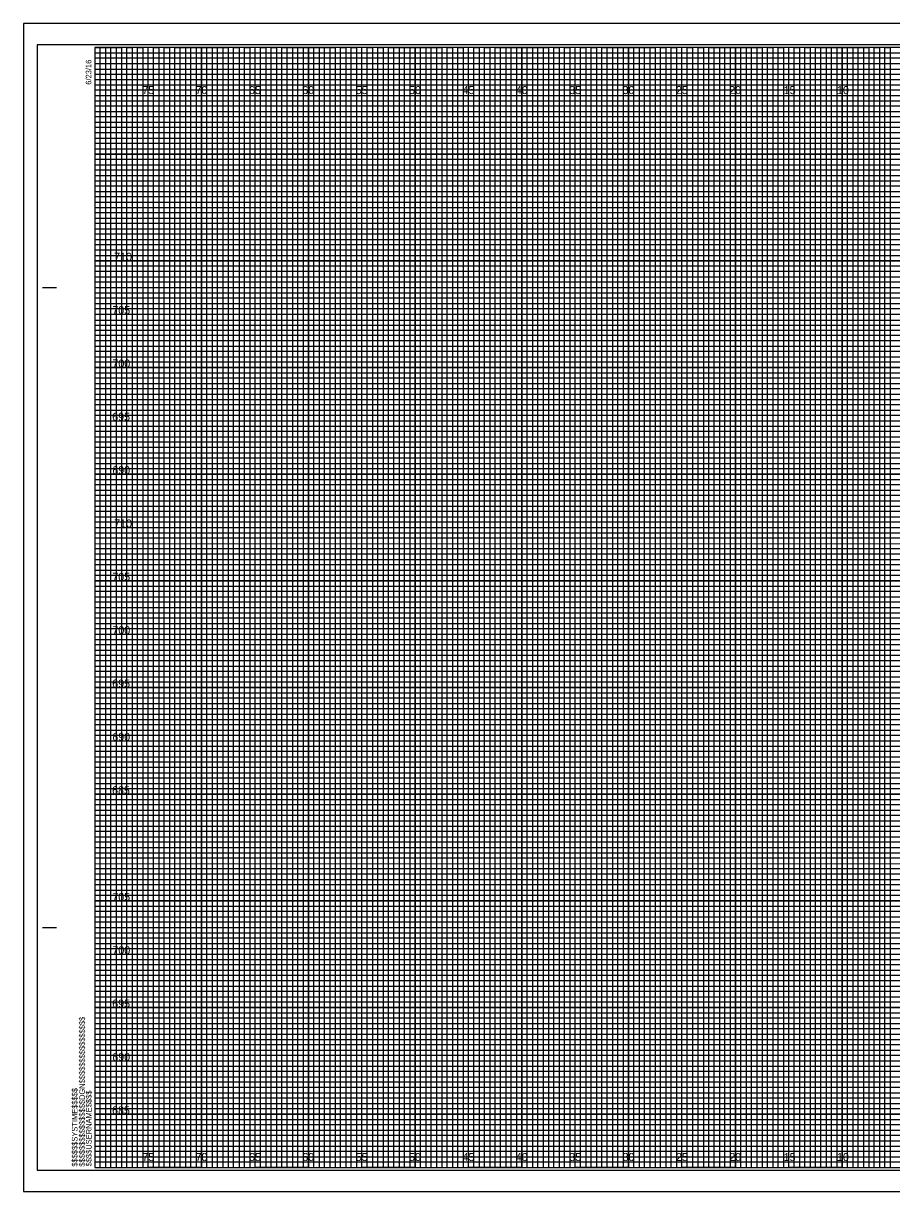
# Model space of a CAD drawing. Extents: x -7 to 162, y 108 to 217.
# Drawn here: x -6.7 to 74.6, y 107.8 to 217.2 of the extents above; entities that cross this region are included whole.
import ezdxf

# ---------------------------------------------------------------- set-up
doc = ezdxf.new("R2010")
doc.units = 0
for name, color, linetype in [('Exist Cross Section Cell', 7, 'Continuous'), ('Exist XS Ground Line', 7, 'Continuous'), ('Prop CMT Pvmt Course 1', 7, 'Continuous'), ('Prop CMT Pvmt Course 3', 7, 'Continuous'), ('Prop CMT Pvmt Surface', 7, 'Continuous'), ('Prop CMT Pvmt Surface Shoulder', 7, 'Continuous'), ('Prop CMT Shld Paved Course 1', 7, 'Continuous'), ('Prop CMT Shld Paved Course 2', 7, 'Continuous'), ('Prop CMT Shld Paved Course 3', 7, 'Continuous'), ('Prop CMT Subgrade Earthwork', 7, 'Continuous'), ('Scratch_Level_8', 7, 'Continuous')]:
    doc.layers.add(name, color=color, linetype=linetype)

msp = doc.modelspace()

# ---------------------------------------------------------------- linework, layer by layer
at = {"layer": 'Exist XS Ground Line'}
for p, q in [((5, 215), (0, 215)), ((5, 110), (5, 215)), ((15, 215), (10, 215)), ((10, 215), (10, 110)), ((15, 110), (15, 215)), ((25, 215), (20, 215)), ((20, 215), (20, 110)), ((25, 110), (25, 215)), ((35, 215), (30, 215)), ((30, 215), (30, 110)), ((35, 110), (35, 215)), ((45, 215), (40, 215)), ((40, 215), (40, 110)), ((45, 110), (45, 215)), ((55, 215), (50, 215)), ((50, 215), (50, 110)), ((55, 110), (55, 215)), ((65, 215), (60, 215)), ((60, 215), (60, 110)), ((65, 110), (65, 215)), ((75, 215), (70, 215)), ((70, 215), (70, 110)), ((10, 110), (5, 110)), ((20, 110), (15, 110)), ((30, 110), (25, 110)), ((40, 110), (35, 110)), ((50, 110), (45, 110)), ((60, 110), (55, 110)), ((70, 110), (65, 110))]:
    msp.add_line(p, q, dxfattribs=at)
for points in [[(0, 210), (160, 210), (160, 205), (0, 205)], [(0, 200), (160, 200), (160, 195), (0, 195)], [(0, 190), (160, 190), (160, 185), (0, 185)], [(0, 180), (160, 180), (160, 175), (0, 175)], [(0, 170), (160, 170), (160, 165), (0, 165)], [(0, 160), (160, 160), (160, 155), (0, 155)], [(0, 150), (160, 150), (160, 145), (0, 145)], [(0, 140), (160, 140), (160, 135), (0, 135)], [(0, 130), (160, 130), (160, 125), (0, 125)], [(0, 120), (160, 120), (160, 115), (0, 115)]]:
    msp.add_lwpolyline(points, dxfattribs=at)
at = {"layer": 'Prop CMT Pvmt Course 3'}
msp.add_lwpolyline([(-6.7, 107.75), (161.65, 107.75), (161.65, 217.25), (-6.7, 217.25)], close=True, dxfattribs=at)
at = {"layer": 'Prop CMT Pvmt Surface'}
for p, q in [((5, 110), (5, 215)), ((10, 110), (10, 215)), ((15, 110), (15, 215)), ((20, 110), (20, 215)), ((25, 110), (25, 215)), ((30, 110), (30, 215)), ((35, 110), (35, 215)), ((40, 110), (40, 215)), ((45, 110), (45, 215)), ((50, 110), (50, 215)), ((55, 110), (55, 215)), ((60, 110), (60, 215)), ((65, 110), (65, 215)), ((70, 110), (70, 215)), ((0, 210), (160, 210)), ((0, 205), (160, 205)), ((0, 200), (160, 200)), ((0, 195), (160, 195)), ((0, 190), (160, 190)), ((0, 185), (160, 185)), ((0, 180), (160, 180)), ((0, 175), (160, 175)), ((0, 170), (160, 170)), ((0, 165), (160, 165)), ((0, 160), (160, 160)), ((0, 155), (160, 155)), ((0, 150), (160, 150)), ((0, 145), (160, 145)), ((0, 140), (160, 140)), ((0, 135), (160, 135)), ((0, 130), (160, 130)), ((0, 125), (160, 125)), ((0, 120), (160, 120)), ((0, 115), (160, 115))]:
    msp.add_line(p, q, dxfattribs=at)
at = {"layer": 'Prop CMT Pvmt Surface Shoulder'}
for p, q in [((161.65, 217.25), (-6.7, 217.25)), ((-6.7, 217.25), (-6.7, 107.75)), ((-6.7, 107.75), (161.65, 107.75))]:
    msp.add_line(p, q, dxfattribs=at)
at = {"layer": 'Prop CMT Shld Paved Course 1'}
for p, q in [((0, 214.5), (130, 214.5)), ((130, 213.99), (0, 213.99)), ((0, 213.99), (0, 213.5)), ((0, 213.5), (130, 213.5)), ((130, 212.94), (0, 212.94)), ((0, 212.94), (0, 212)), ((0, 212), (160, 212))]:
    msp.add_line(p, q, dxfattribs=at)
for points in [[(0, 211.5), (135, 211.5), (160, 211.5), (160, 211), (0, 211)], [(0, 210.5), (160, 210.5), (160, 209.5), (0, 209.5)], [(0, 209), (160, 209), (160, 208.5), (0, 208.49)], [(0, 208), (160, 208), (160, 207), (0, 207)], [(0, 206.5), (160, 206.5), (160, 206), (0, 206)], [(0, 205.5), (160, 205.5), (160, 204.5), (0, 204.5)], [(0, 204), (160, 204), (160, 203.5), (0, 203.5)], [(0, 203), (160, 203), (160, 202), (0, 202)], [(0, 201.5), (160, 201.5), (160, 201), (0, 201)], [(0, 200.5), (160, 200.5), (160, 199.5), (0, 199.5)], [(0, 199), (160, 199), (160, 198.5), (0, 198.5)], [(0, 198), (160, 198), (160, 196.97), (160, 196.5), (160, 196), (0, 196)], [(0, 197), (160, 197), (160, 196.5), (0, 196.5)], [(0, 195.5), (160, 195.5), (160, 194.5), (0, 194.52)], [(0, 194.52), (160, 194.5), (160, 194), (0, 194)], [(0, 193.5), (160, 193.5), (160, 193), (0, 193)], [(0, 192), (160, 192), (160, 191.5), (0, 191.5)], [(0, 191), (160, 191), (160, 190.5), (0, 190.5)], [(-0.04, 189.44), (160, 189.44), (160, 188.94), (-0.04, 188.94)], [(0, 188.5), (160, 188.5), (160, 188), (0, 188)], [(0, 187), (160, 187), (160, 186.5), (0, 186.5)], [(0, 186), (160, 186), (160, 185.5), (0, 185.5)], [(0, 184.5), (160, 184.5), (160, 184), (0, 184)], [(0, 183.5), (160, 183.5), (160, 183), (0, 183)], [(0, 182), (160, 182), (160, 181.5), (0, 181.5)], [(0, 181), (160, 181), (160, 180.5), (0, 180.5)], [(0, 179.5), (160, 179.5), (160, 178.99), (0, 179)], [(0, 178.5), (160, 178.5), (160, 178), (0, 178)], [(0, 177), (160, 177), (160, 176.5), (0, 176.5)], [(0, 176), (160, 176), (160, 175.5), (0, 175.5)], [(0, 174.5), (160, 174.5), (160, 174), (0, 174)], [(0, 173.5), (160, 173.5), (160, 173), (0, 173)], [(0, 172), (160, 172), (160, 171.5), (0, 171.5)], [(0, 171), (160, 171), (160, 170.5), (0, 170.5)], [(0, 169.5), (160, 169.5), (160, 169), (0, 169)], [(0, 168.5), (160.03, 168.46), (160, 168), (0, 168)], [(0, 167), (160, 167), (160, 166.5), (0, 166.5)], [(0, 166), (160, 166), (160, 165.5), (0, 165.5)], [(0, 164.5), (160, 164.5), (160, 164), (0, 164)], [(0, 163.5), (160, 163.5), (160, 163), (0, 163)], [(0, 162), (160, 162), (160, 161.5), (0, 161.5)], [(0, 161), (160, 161), (160, 160.5), (0, 160.5)], [(0, 159.5), (160, 159.5), (160, 159), (0, 159)], [(0, 158.5), (160, 158.5), (160, 158), (0, 158)], [(0, 157), (160, 157), (160, 156.5), (0, 156.5)], [(0, 156), (160, 156), (160, 155.5), (0, 155.5)], [(0, 154.5), (160, 154.5), (160, 154), (0, 154)], [(0, 153.5), (160, 153.5), (160, 153), (0, 153)], [(0, 152), (160, 152), (160, 151.5), (0, 151.5)], [(0, 151), (160, 151), (160, 150.5), (0, 150.5)], [(0, 149.5), (160, 149.5), (160, 148.99), (0, 149)], [(0, 148.5), (160, 148.5), (160, 148), (0, 148)], [(0, 147), (160, 147), (160, 146.5), (0, 146.5)], [(0, 146), (160, 146), (160, 145.5), (0, 145.5)], [(0, 144.5), (160, 144.5), (160, 144), (0, 144)], [(0, 143.5), (160, 143.5), (160, 143), (0, 143)], [(0, 142), (160, 142), (160, 141.5), (0, 141.5)], [(0, 141), (160, 141), (160, 140.5), (0, 140.5)], [(0, 139.5), (160, 139.5), (160, 139), (0, 139)], [(0, 138.5), (160.03, 138.46), (160, 138), (0, 138)], [(0, 137), (160, 137), (160, 136.5), (0, 136.5)], [(0, 136), (160, 136), (160, 135.5), (0, 135.5)], [(0, 134.5), (160, 134.5), (160, 134), (0, 134)], [(0, 133.5), (160, 133.5), (160, 133), (0, 133)], [(0, 132), (160, 132), (160, 131.5), (0, 131.5)], [(0, 131), (160, 131), (160, 130.5), (0, 130.5)], [(0, 129.5), (160, 129.5), (160, 129), (0, 129)], [(0, 128.5), (160, 128.5), (160, 128), (0, 128)], [(0, 127), (160, 127), (160, 126.5), (0, 126.5)], [(0, 126), (160, 126), (160, 125.5), (0, 125.5)], [(0, 124.5), (160, 124.5), (160, 124), (0, 124)], [(0, 123.5), (160, 123.5), (160, 123), (0, 123)], [(0, 122), (160, 122), (160, 121.5), (0, 121.5)], [(0, 121), (160, 121), (160, 120.5), (0, 120.5)], [(0, 119.5), (160, 119.5), (160, 119), (0, 119)], [(0, 118.5), (160, 118.5), (160, 118), (0, 118)], [(0, 117), (160, 117), (160, 116.5), (0, 116.5)], [(0, 116), (160, 116), (160, 115.5), (0, 115.5)], [(0, 114.5), (160, 114.5), (160, 114), (0, 114)], [(0, 113.5), (160, 113.5), (160, 113), (0, 113)], [(0, 112), (160, 112), (160, 111.5), (0, 111.5)], [(0, 111), (160, 111), (160, 110.5), (0, 110.5)]]:
    msp.add_lwpolyline(points, dxfattribs=at)
at = {"layer": 'Prop CMT Shld Paved Course 2'}
for p, q in [((-4.9, 192.5), (-3.65, 192.5)), ((-4.85, 192.5), (-3.6, 192.5)), ((-4.9, 132.5), (-3.65, 132.5)), ((-4.85, 132.5), (-3.6, 132.5)), ((0, 110), (0, 110)), ((0, 110), (0, 110)), ((0, 110), (0, 110)), ((0, 110), (0, 110)), ((0, 110), (0, 110)), ((0, 110), (0, 110)), ((0, 110), (0, 110))]:
    msp.add_line(p, q, dxfattribs=at)
msp.add_lwpolyline([(160, 215), (0, 215), (0, 110), (160, 110)], close=True, dxfattribs=at)
at = {"layer": 'Prop CMT Shld Paved Course 3'}
for points in [[(0, 110), (0.5, 110), (0.5, 215), (1, 215), (1, 110)], [(1, 110), (1.5, 110), (1.5, 215), (2, 215), (2, 110)], [(2.5, 110), (3, 110), (3, 215), (3.5, 215), (3.5, 110)], [(3.5, 110), (4, 110), (4, 215), (4.5, 215), (4.5, 110)], [(5, 110), (5.5, 110), (5.5, 215), (6, 215), (6, 110)], [(6, 110), (6.5, 110), (6.5, 215), (7, 215), (7, 110)], [(7.5, 110), (8, 110), (8, 215), (8.5, 215), (8.5, 110)], [(8.5, 110), (9, 110), (9, 215), (9.5, 215), (9.5, 110)], [(10, 110), (10.5, 110), (10.5, 215), (11, 215), (11, 110)], [(11, 110), (11.5, 110), (11.5, 215), (12, 215), (12, 110)], [(12.5, 110), (13, 110), (13, 215), (13.5, 215), (13.5, 110)], [(13.5, 110), (14, 110), (14, 215), (14.5, 215), (14.5, 110)], [(15, 110), (15.5, 110), (15.5, 215), (16, 215), (16, 110)], [(16, 110), (16.5, 110), (16.5, 215), (17, 215), (17, 110)], [(17.5, 110), (18, 110), (18, 215), (18.5, 215), (18.5, 110)], [(18.5, 110), (19, 110), (19, 215), (19.5, 215), (19.5, 110)], [(20, 110), (20.5, 110), (20.5, 215), (21, 215), (21, 110)], [(21, 110), (21.5, 110), (21.5, 215), (22, 215), (22, 110)], [(22.5, 110), (23, 110), (23, 215), (23.5, 215), (23.5, 110)], [(23.5, 110), (24, 110), (24, 215), (24.5, 215), (24.5, 110)], [(25, 110), (25.5, 110), (25.5, 215), (26, 215), (26, 110)], [(26, 110), (26.5, 110), (26.5, 215), (27, 215), (27, 110)], [(27.5, 110), (28, 110), (28, 215), (28.5, 215), (28.5, 110)], [(28.5, 110), (29, 110), (29, 215), (29.5, 215), (29.5, 110)], [(30, 110), (30.5, 110), (30.5, 215), (31, 215), (31, 110)], [(31, 110), (31.5, 110), (31.5, 215), (32, 215), (32, 110)], [(32.5, 110), (33, 110), (33, 215), (33.5, 215), (33.5, 110)], [(33.5, 110), (34, 110), (34, 215), (34.5, 215), (34.5, 110)], [(35, 110), (35.5, 110), (35.5, 215), (36, 215), (36, 110)], [(36, 110), (36.5, 110), (36.5, 215), (37, 215), (37, 110)], [(37.5, 110), (38, 110), (38, 215), (38.5, 215), (38.5, 110)], [(38.5, 110), (39, 110), (39, 215), (39.5, 215), (39.5, 110)], [(40, 110), (40.5, 110), (40.5, 215), (41, 215), (41, 110)], [(41, 110), (41.5, 110), (41.5, 215), (42, 215), (42, 110)], [(42.5, 110), (43, 110), (43, 215), (43.5, 215), (43.5, 110)], [(43.5, 110), (44, 110), (44, 215), (44.5, 215), (44.5, 110)], [(45, 110), (45.5, 110), (45.5, 215), (46, 215), (46, 110)], [(46, 110), (46.5, 110), (46.5, 215), (47, 215), (47, 110)], [(47.5, 110), (48, 110), (48, 215), (48.5, 215), (48.5, 110)], [(48.5, 110), (49, 110), (49, 215), (49.5, 215), (49.5, 110)], [(50, 110), (50.5, 110), (50.5, 215), (51, 215), (51, 110)], [(51, 110), (51.5, 110), (51.5, 215), (52, 215), (52, 110)], [(52.5, 110), (53, 110), (53, 215), (53.5, 215), (53.5, 110)], [(53.5, 110), (54, 110), (54, 215), (54.5, 215), (54.5, 110)], [(55, 110), (55.5, 110), (55.5, 215), (56, 215), (56, 110)], [(56, 110), (56.5, 110), (56.5, 215), (57, 215), (57, 110)], [(57.5, 110), (58, 110), (58, 215), (58.5, 215), (58.5, 110)], [(58.5, 110), (59, 110), (59, 215), (59.5, 215), (59.5, 110)], [(60, 110), (60.5, 110), (60.5, 215), (61, 215), (61, 110)], [(61, 110), (61.5, 110), (61.5, 215), (62, 215), (62, 110)], [(62.5, 110), (63, 110), (63, 215), (63.5, 215), (63.5, 110)], [(63.5, 110), (64, 110), (64, 215), (64.5, 215), (64.5, 110)], [(65, 110), (65.5, 110), (65.5, 215), (66, 215), (66, 110)], [(66, 110), (66.5, 110), (66.5, 215), (67, 215), (67, 110)], [(67.5, 110), (68, 110), (68, 215), (68.5, 215), (68.5, 110)], [(68.5, 110), (69, 110), (69, 215), (69.5, 215), (69.5, 110)], [(70, 110), (70.5, 110), (70.5, 215), (71, 215), (71, 110)], [(71, 110), (71.5, 110), (71.5, 215), (72, 215), (72, 110)], [(72.5, 110), (73, 110), (73, 215), (73.5, 215), (73.5, 110)], [(73.5, 110), (74, 110), (74, 215), (74.5, 215), (74.5, 110)]]:
    msp.add_lwpolyline(points, dxfattribs=at)
at = {"layer": 'Prop CMT Subgrade Earthwork'}
msp.add_lwpolyline([(-5.4, 109.75), (161.2, 109.75), (161.2, 215.25), (-5.4, 215.25)], close=True, dxfattribs=at)
at = {"layer": 'Scratch_Level_8'}
for points in [[(0, 215), (2.5, 215), (2.5, 110), (7.5, 110), (7.5, 215), (12.5, 215), (12.5, 110), (17.5, 110), (17.5, 215), (22.5, 215), (22.5, 110), (27.5, 110), (27.5, 215), (32.5, 215), (32.5, 110), (37.5, 110), (37.5, 215), (42.5, 215), (42.5, 110), (47.5, 110), (47.5, 215), (52.5, 215), (52.5, 110), (57.5, 110), (57.5, 215), (62.5, 215), (62.5, 110), (67.5, 110), (67.5, 215), (72.5, 215), (72.5, 110), (77.5, 110)], [(0, 212.5), (137.5, 212.5)], [(0, 202.5), (160, 202.5), (160, 207.5), (0, 207.5)], [(0, 192.5), (160, 192.5), (160, 197.5), (0, 197.5)], [(0, 182.5), (160, 182.5), (160, 187.5), (0, 187.5)], [(0, 172.5), (160, 172.5), (160, 177.5), (0, 177.5)], [(0, 162.5), (160, 162.5), (160, 167.5), (0, 167.5)], [(0, 152.5), (160, 152.5), (160, 157.5), (0, 157.5)], [(0, 142.5), (160, 142.5), (160, 147.5), (0, 147.5)], [(0, 132.5), (160, 132.5), (160, 137.5), (0, 137.5)], [(0, 122.5), (160, 122.5), (160, 127.5), (0, 127.5)], [(0, 112.5), (160, 112.5), (160, 117.5), (0, 117.5)]]:
    msp.add_lwpolyline(points, dxfattribs=at)

# ---------------------------------------------------------------- texts
at = {"layer": 'Exist Cross Section Cell'}
for s, p in [('75', (4.44, 210.62)), ('70', (9.43, 210.62)), ('65', (14.44, 210.62)), ('60', (19.43, 210.62)), ('55', (24.44, 210.62)), ('50', (29.43, 210.62)), ('45', (34.44, 210.62)), ('40', (39.43, 210.62)), ('35', (44.44, 210.62)), ('30', (49.43, 210.62)), ('25', (54.44, 210.62)), ('20', (59.43, 210.62)), ('15', (64.53, 210.62)), ('10', (69.52, 210.62)), ('75', (4.44, 110.62)), ('70', (9.43, 110.62)), ('65', (14.44, 110.62)), ('60', (19.43, 110.62)), ('55', (24.44, 110.62)), ('50', (29.43, 110.62)), ('45', (34.44, 110.62)), ('40', (39.43, 110.62)), ('35', (44.44, 110.62)), ('30', (49.43, 110.62)), ('25', (54.44, 110.62)), ('20', (59.43, 110.62)), ('15', (64.53, 110.62)), ('10', (69.52, 110.62))]:
    msp.add_text(s, height=0.75, dxfattribs=at).set_placement(p)
at = {"layer": 'Prop CMT Pvmt Course 1'}
for s, p in [('710', (1.8, 195)), ('705', (1.63, 190)), ('700', (1.64, 185)), ('695', (1.62, 180)), ('690', (1.63, 175)), ('710', (1.8, 170)), ('705', (1.63, 165)), ('700', (1.64, 160)), ('695', (1.62, 155)), ('690', (1.63, 150)), ('685', (1.61, 145)), ('705', (1.63, 135)), ('700', (1.64, 130)), ('695', (1.62, 125)), ('690', (1.63, 120)), ('685', (1.61, 115))]:
    msp.add_text(s, height=0.75, dxfattribs=at).set_placement(p)
at = {"layer": 'Prop CMT Shld Paved Course 2'}
for s, p in [('6/23/16', (-0.33, 211.5)), ('$$$$$$$$$$$$$$$$DGN$$$$$$$$$$$$$$$$', (-0.94, 110.09)), ('$$$$$$SYSTIME$$$$$', (-1.63, 110.09)), ('$$$$USERNAME$$$$', (-0.31, 110.12))]:
    msp.add_text(s, height=0.525, rotation=90, dxfattribs=at).set_placement(p)

doc.saveas('drawing.dxf')
